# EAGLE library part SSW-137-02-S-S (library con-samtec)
THROUGH-HOLE .025" SQ POST SOCKET Source: Samtec SSW.pdf
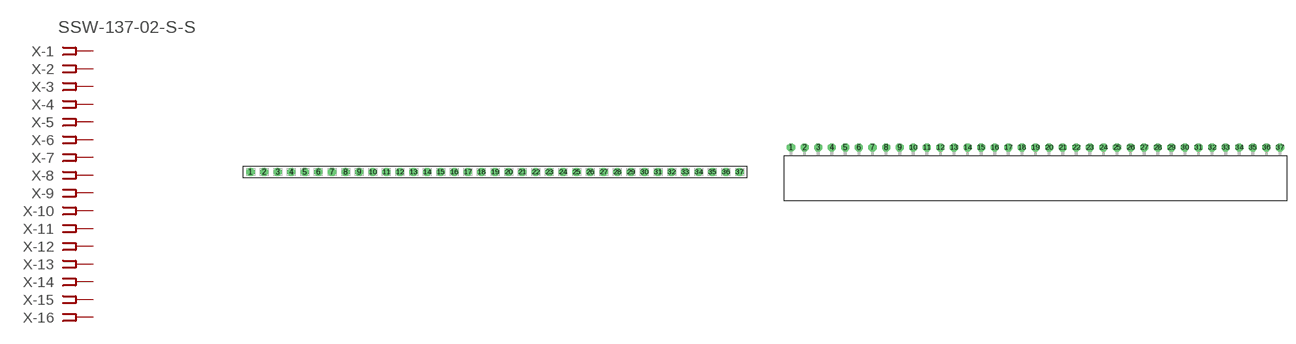
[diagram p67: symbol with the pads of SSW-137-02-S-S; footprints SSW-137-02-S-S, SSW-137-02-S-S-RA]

Designator prefix X; gates -1=FPINV -2=FPIN -3=FPIN -4=FPIN -5=FPIN -6=FPIN -7=FPIN -8=FPIN -9=FPIN -10=FPIN -11=FPIN -12=FPIN -13=FPIN -14=FPIN -15=FPIN -16=FPIN -17=FPIN -18=FPIN -19=FPIN -20=FPIN -21=FPIN -22=FPIN -23=FPIN -24=FPIN -25=FPIN -26=FPIN -27=FPIN -28=FPIN -29=FPIN -30=FPIN -31=FPIN -32=FPIN -33=FPIN -34=FPIN -35=FPIN -36=FPIN -37=FPIN

## SSW-137-02-S-S (OC_FARNELL: unknown; OC_NEWARK: unknown)  [SSW-137-02-S-S]
1  -1:1  pas
2  -2:1  pas
3  -3:1  pas
4  -4:1  pas
5  -5:1  pas
6  -6:1  pas
7  -7:1  pas
8  -8:1  pas
9  -9:1  pas
10  -10:1  pas
11  -11:1  pas
12  -12:1  pas
13  -13:1  pas
14  -14:1  pas
15  -15:1  pas
16  -16:1  pas
17  -17:1  pas
18  -18:1  pas
19  -19:1  pas
20  -20:1  pas
21  -21:1  pas
22  -22:1  pas
23  -23:1  pas
24  -24:1  pas
25  -25:1  pas
26  -26:1  pas
27  -27:1  pas
28  -28:1  pas
29  -29:1  pas
30  -30:1  pas
31  -31:1  pas
32  -32:1  pas
33  -33:1  pas
34  -34:1  pas
35  -35:1  pas
36  -36:1  pas
37  -37:1  pas

## SSW-137-02-S-S-RA (OC_FARNELL: unknown; OC_NEWARK: unknown)  [SSW-137-02-S-S-RA]
Pads as for SSW-137-02-S-S

## Footprint SSW-137-02-S-S (pad centres in mm)
THROUGH-HOLE .025" SQ POST SOCKET Source: Samtec SSW.pdf
drill 1 pad 1.5 octagon: 1 -45.72,0; 2 -43.18,0; 3 -40.64,0; 4 -38.1,0; 5 -35.56,0; 6 -33.02,0; 7 -30.48,0; 8 -27.94,0; 9 -25.4,0; 10 -22.86,0; 11 -20.32,0; 12 -17.78,0; 13 -15.24,0; 14 -12.7,0; 15 -10.16,0; 16 -7.62,0; 17 -5.08,0; 18 -2.54,0; 19 0,0; 20 2.54,0; 21 5.08,0; 22 7.62,0; 23 10.16,0; 24 12.7,0; 25 15.24,0; 26 17.78,0; 27 20.32,0; 28 22.86,0; 29 25.4,0; 30 27.94,0; 31 30.48,0; 32 33.02,0; 33 35.56,0; 34 38.1,0; 35 40.64,0; 36 43.18,0; 37 45.72,0

## Footprint SSW-137-02-S-S-RA (pad centres in mm)
THROUGH-HOLE .025" SQ POST SOCKET Source: Samtec SSW.pdf
drill 1 pad 1.5 octagon: 1 -45.72,1.524; 2 -43.18,1.524; 3 -40.64,1.524; 4 -38.1,1.524; 5 -35.56,1.524; 6 -33.02,1.524; 7 -30.48,1.524; 8 -27.94,1.524; 9 -25.4,1.524; 10 -22.86,1.524; 11 -20.32,1.524; 12 -17.78,1.524; 13 -15.24,1.524; 14 -12.7,1.524; 15 -10.16,1.524; 16 -7.62,1.524; 17 -5.08,1.524; 18 -2.54,1.524; 19 0,1.524; 20 2.54,1.524; 21 5.08,1.524; 22 7.62,1.524; 23 10.16,1.524; 24 12.7,1.524; 25 15.24,1.524; 26 17.78,1.524; 27 20.32,1.524; 28 22.86,1.524; 29 25.4,1.524; 30 27.94,1.524; 31 30.48,1.524; 32 33.02,1.524; 33 35.56,1.524; 34 38.1,1.524; 35 40.64,1.524; 36 43.18,1.524; 37 45.72,1.524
